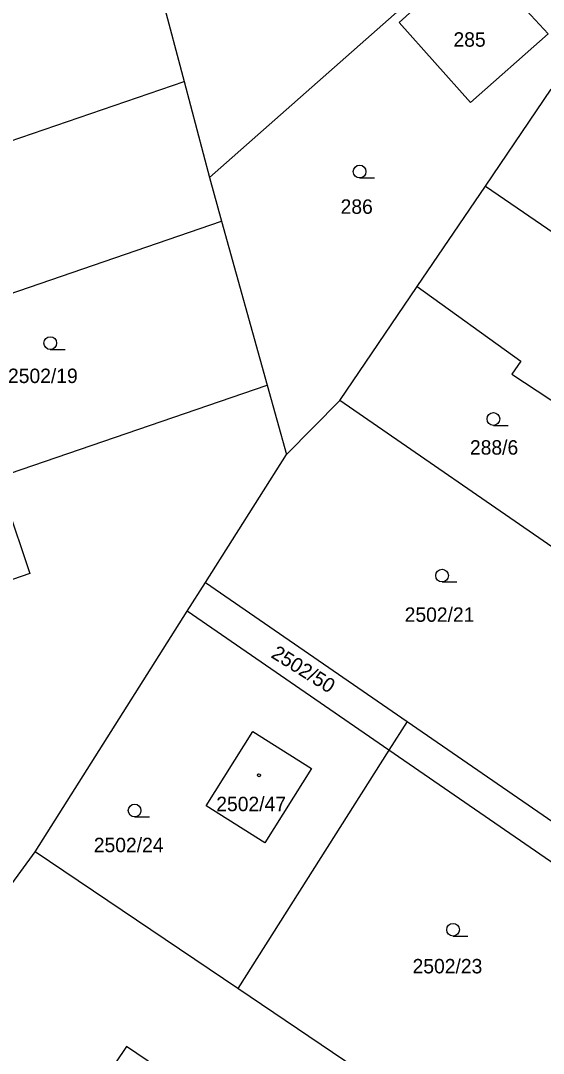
# Model space of a CAD drawing. Extents: x -558358 to -557517, y -1073785 to -1073189.
# Drawn here: x -558259.4 to -558197.8, y -1073448.9 to -1073327.3 of the extents above; entities that cross this region are included whole.
import ezdxf

# ---------------------------------------------------------------- set-up
doc = ezdxf.new("R2010")
doc.units = 0
for name, color, linetype in [('Hranice parcel', 7, 'Continuous'), ('Parcelní čísla', 7, 'Continuous'), ('Značky budov', 7, 'Continuous'), ('Značky kultur', 7, 'Continuous')]:
    doc.layers.add(name, color=color, linetype=linetype)

msp = doc.modelspace()

# ---------------------------------------------------------------- linework, layer by layer
at = {"layer": 'Hranice parcel'}
for p, q in [((-558245.27, -1073315.03), (-558240.15, -1073334.41)), ((-558305.76, -1073356.92), (-558240.15, -1073334.41)), ((-558240.15, -1073334.41), (-558237.16, -1073345.74)), ((-558204.65, -1073346.74), (-558196.91, -1073335.32)), ((-558237.16, -1073345.74), (-558235.73, -1073350.87)), ((-558212.67, -1073358.56), (-558204.65, -1073346.74)), ((-558204.65, -1073346.74), (-558176.94, -1073365.71)), ((-558300.65, -1073373.14), (-558235.73, -1073350.87)), ((-558235.73, -1073350.87), (-558230.35, -1073370.17)), ((-558221.79, -1073372.01), (-558212.67, -1073358.56)), ((-558212.67, -1073358.56), (-558200.47, -1073367.38)), ((-558294.64, -1073392.22), (-558230.35, -1073370.17)), ((-558230.35, -1073370.17), (-558228.07, -1073378.34)), ((-558228.07, -1073378.34), (-558221.79, -1073372.01)), ((-558193.18, -1073391.75), (-558221.79, -1073372.01)), ((-558237.63, -1073393.44), (-558228.07, -1073378.34)), ((-558239.77, -1073396.82), (-558237.63, -1073393.44)), ((-558237.63, -1073393.44), (-558213.88, -1073409.79)), ((-558257.7, -1073425.14), (-558239.77, -1073396.82)), ((-558216.02, -1073413.17), (-558239.77, -1073396.82)), ((-558213.88, -1073409.79), (-558216.02, -1073413.17)), ((-558213.88, -1073409.79), (-558196.71, -1073421.6)), ((-558216.02, -1073413.17), (-558233.8, -1073441.26)), ((-558274.97, -1073448.74), (-558257.7, -1073425.14)), ((-558233.8, -1073441.26), (-558257.7, -1073425.14)), ((-558202.26, -1073462.53), (-558233.8, -1073441.26))]:
    msp.add_line(p, q, dxfattribs=at)
for points in [[(-558237.16, -1073345.74), (-558202.67, -1073315.29), (-558195.58, -1073320.33), (-558174.53, -1073305.05)], [(-558197.27, -1073328.8), (-558205.94, -1073319.43), (-558214.79, -1073327.48), (-558206.42, -1073336.91), (-558197.27, -1073328.8)], [(-558200.47, -1073367.38), (-558201.52, -1073368.91), (-558186.39, -1073378.87)], [(-558278.42, -1073389.81), (-558261.13, -1073384.05), (-558258.31, -1073392.37), (-558262.58, -1073393.82), (-558262, -1073395.6), (-558267.81, -1073397.55), (-558268.37, -1073395.87), (-558275.59, -1073398.26), (-558278.42, -1073389.81)], [(-558232.07, -1073410.99), (-558225.13, -1073415.34), (-558230.62, -1073424.08), (-558237.55, -1073419.73), (-558232.07, -1073410.99)], [(-558202.26, -1073462.53), (-558188.73, -1073442.87), (-558187.31, -1073436.01), (-558191.04, -1073430.36), (-558216.02, -1073413.17)], [(-558252.58, -1073492.61), (-558249.44, -1073487.92), (-558239.75, -1073494.46), (-558236.97, -1073490.34), (-558223.28, -1073470.09), (-558220.49, -1073465.96), (-558246.94, -1073448.09), (-558263.73, -1073472.95)]]:
    msp.add_lwpolyline(points, dxfattribs=at)
at = {"layer": 'Značky budov'}
msp.add_circle((-558231.33, -1073416.12), 0.175, dxfattribs=at)
at = {"layer": 'Značky kultur'}
for p, q in [((-558219.47, -1073345.78), (-558217.72, -1073345.78)), ((-558255.92, -1073365.99), (-558254.17, -1073365.99)), ((-558203.7, -1073374.92), (-558201.95, -1073374.92)), ((-558209.75, -1073393.36), (-558208, -1073393.36)), ((-558245.99, -1073421.03), (-558244.24, -1073421.03)), ((-558208.46, -1073435.07), (-558206.71, -1073435.07))]:
    msp.add_line(p, q, dxfattribs=at)
for centre in [(-558219.47, -1073345.03), (-558255.92, -1073365.24), (-558203.7, -1073374.17), (-558209.75, -1073392.61), (-558245.99, -1073420.28), (-558208.46, -1073434.32)]:
    msp.add_circle(centre, 0.75, dxfattribs=at)

# ---------------------------------------------------------------- texts
at = {"layer": 'Parcelní čísla'}
for s, p in [('285', (-558208.41, -1073330.33)), ('286', (-558221.71, -1073350.01)), ('2502/19', (-558260.9, -1073369.94)), ('288/6', (-558206.47, -1073378.37)), ('2502/21', (-558214.16, -1073398.06)), ('2502/47', (-558236.36, -1073420.36)), ('2502/24', (-558250.79, -1073425.19)), ('2502/23', (-558213.23, -1073439.46))]:
    msp.add_text(s, height=1.7, dxfattribs=at).set_placement(p)
msp.add_text('2502/50', height=1.7, rotation=328, dxfattribs=at).set_placement((-558230.02, -1073402.18))

doc.saveas('drawing.dxf')
